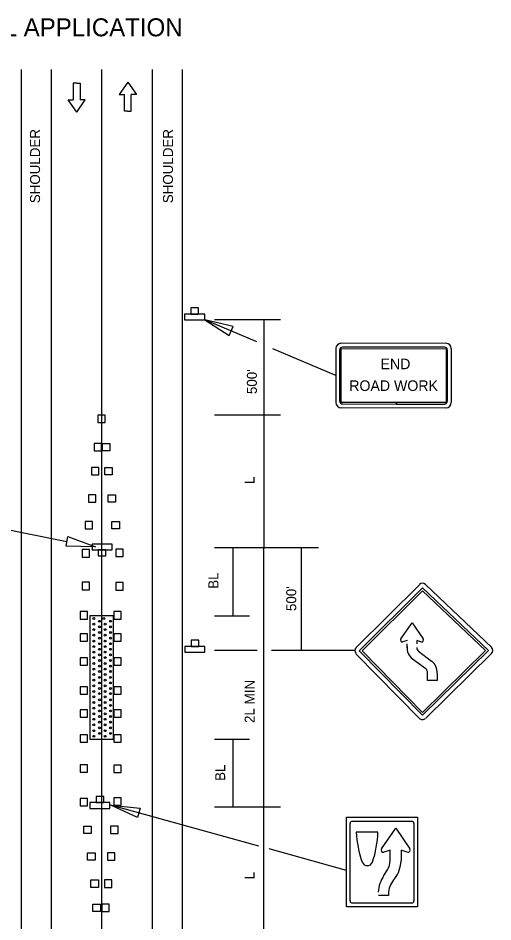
# Model space of a CAD drawing. Extents: x 612.48 to 619.85, y 611.03 to 621.02.
# Drawn here: x 616.73 to 619.58, y 615.59 to 621.02 of the extents above; entities that cross this region are included whole.
import ezdxf

# ---------------------------------------------------------------- set-up
doc = ezdxf.new("R2010")
doc.units = 0
for name, color, linetype in [('DETL-DIMS', 7, 'Continuous'), ('DETL-LINE', 7, 'Continuous'), ('DETL-NOTE', 7, 'Continuous'), ('DETL-TITL', 7, 'Continuous'), ('USER-BORD', 7, 'Continuous')]:
    doc.layers.add(name, color=color, linetype=linetype)

# ---------------------------------------------------------------- blocks, each defined once
blk = doc.blocks.new('TD')
at = {"layer": 'USER-BORD'}
for p, q in [((0, 0), (-0.0054, -0.0077)), ((0, 0), (0.0054, -0.0077)), ((-0.0054, -0.0077), (-0.0021, -0.0077)), ((-0.0021, -0.018), (-0.0021, -0.0077)), ((0.0021, -0.018), (0.0021, -0.0077)), ((0.0054, -0.0077), (0.0021, -0.0077)), ((-0.0002, -0.018), (-0.0021, -0.018)), ((-0.0002, -0.018), (0.0002, -0.018)), ((0.0002, -0.018), (0.0021, -0.018))]:
    blk.add_line(p, q, dxfattribs=at)

msp = doc.modelspace()

# ---------------------------------------------------------------- linework, layer by layer
at = {"layer": 'DETL-DIMS'}
for p, q in [((618.1645, 619.0756), (617.8515, 619.2089)), ((618.3066, 619.2089), (617.9108, 619.2089)), ((618.2067, 619.2089), (618.2067, 618.6361)), ((618.6389, 618.8737), (618.2597, 619.0351)), ((618.3066, 618.6361), (617.9108, 618.6361)), ((618.2067, 618.6361), (618.2067, 617.8375)), ((616.1861, 618.0434), (617.0233, 617.877)), ((618.5355, 617.8375), (617.9108, 617.8375)), ((618.0216, 617.429), (618.0216, 617.8375)), ((618.2067, 616.2804), (618.2067, 617.8375)), ((618.4333, 617.2208), (618.4333, 617.8375)), ((617.9108, 617.429), (618.121, 617.429)), ((618.1661, 617.2208), (617.9108, 617.2208)), ((618.754, 617.2208), (618.2518, 617.2208)), ((617.9108, 616.6888), (618.121, 616.6888)), ((618.0216, 616.2804), (618.0216, 616.6888)), ((618.1773, 616.0448), (617.2875, 616.2915)), ((617.9108, 616.2804), (618.3066, 616.2804)), ((618.2067, 615.4818), (618.2067, 616.2804)), ((618.7026, 615.8991), (618.2381, 616.0279))]:
    msp.add_line(p, q, dxfattribs=at)
for points in [[(617.9988, 619.1147), (618.0218, 619.1678), (617.8515, 619.2089)], [(617.0175, 617.8487), (617.0291, 617.9053), (617.194, 617.8431)], [(617.463, 616.2728), (617.4473, 616.2172), (617.2875, 616.2915)]]:
    msp.add_lwpolyline(points, close=True, dxfattribs=at)
at = {"layer": 'DETL-LINE'}
for p, q in [((616.7487, 620.7128), (616.7487, 612.917)), ((616.9288, 620.7128), (616.9288, 612.917)), ((617.232, 612.917), (617.232, 620.7128)), ((617.5352, 620.7128), (617.5352, 612.917)), ((617.7153, 620.7128), (617.7153, 612.917)), ((619.3014, 619.0673), (618.671, 619.068)), ((618.671, 619.0347), (619.302, 619.0353)), ((618.671, 618.7115), (618.671, 619.0347)), ((619.2918, 619.0436), (618.6799, 619.0449)), ((619.2918, 619.0436), (619.2918, 619.0436)), ((619.302, 619.0353), (619.3014, 618.7115)), ((618.662, 619.0264), (618.662, 618.7211)), ((619.3097, 618.7211), (619.3097, 619.0251)), ((619.0044, 618.7121), (618.671, 618.7115)), ((618.6806, 618.7032), (619.0038, 618.7025)), ((619.0038, 618.7025), (619.0044, 618.7121)), ((619.0044, 618.7121), (619.0038, 618.7025)), ((619.0038, 618.7025), (619.2924, 618.7025)), ((619.3014, 618.7115), (619.0044, 618.7121)), ((617.2436, 617.8294), (617.2436, 617.8294)), ((617.2436, 617.8294), (617.2436, 617.8294)), ((617.2436, 617.8294), (617.2436, 617.8294)), ((617.2436, 617.8294), (617.2436, 617.8294)), ((617.3032, 617.429), (617.1598, 617.429)), ((617.1598, 617.429), (617.1598, 616.6888)), ((617.1848, 617.4127), (617.1848, 617.4127)), ((617.2522, 617.4127), (617.2522, 617.4127)), ((617.3032, 616.6888), (617.3032, 617.429)), ((617.1848, 617.379), (617.1848, 617.379)), ((617.1848, 617.379), (617.1848, 617.379)), ((617.1848, 617.3463), (617.1848, 617.3463)), ((617.1848, 617.3463), (617.1848, 617.3463)), ((617.2185, 617.3964), (617.2185, 617.3964)), ((617.2185, 617.3636), (617.2185, 617.3636)), ((617.2185, 617.3636), (617.2185, 617.3636)), ((617.2522, 617.379), (617.2522, 617.379)), ((617.2522, 617.3463), (617.2522, 617.3463)), ((617.2523, 617.379), (617.2523, 617.379)), ((617.2523, 617.3463), (617.2523, 617.3463)), ((617.2859, 617.3964), (617.2859, 617.3964)), ((617.2859, 617.3636), (617.2859, 617.3636)), ((617.2859, 617.3636), (617.2859, 617.3636)), ((619.0297, 617.2918), (619.0969, 617.3872)), ((619.0969, 617.3872), (619.1641, 617.2918)), ((617.1848, 617.3126), (617.1848, 617.3126)), ((617.1848, 617.3126), (617.1848, 617.3126)), ((617.2185, 617.3289), (617.2185, 617.3289)), ((617.2185, 617.3289), (617.2185, 617.3289)), ((617.2185, 617.2952), (617.2185, 617.2952)), ((617.2185, 617.2952), (617.2185, 617.2952)), ((617.2522, 617.3126), (617.2522, 617.3126)), ((617.2523, 617.3126), (617.2523, 617.3126)), ((617.2859, 617.3289), (617.2859, 617.3289)), ((617.2859, 617.3289), (617.2859, 617.3289)), ((617.2859, 617.2952), (617.2859, 617.2952)), ((617.2859, 617.2952), (617.2859, 617.2952)), ((617.1848, 617.2779), (617.1848, 617.2779)), ((617.1848, 617.2779), (617.1848, 617.2779)), ((617.1848, 617.2442), (617.1848, 617.2442)), ((617.1848, 617.2442), (617.1848, 617.2442)), ((617.2185, 617.2616), (617.2185, 617.2616)), ((617.2185, 617.2616), (617.2185, 617.2616)), ((617.2522, 617.2779), (617.2522, 617.2779)), ((617.2522, 617.2442), (617.2522, 617.2442)), ((617.2523, 617.2779), (617.2523, 617.2779)), ((617.2523, 617.2442), (617.2523, 617.2442)), ((617.2859, 617.2616), (617.2859, 617.2616)), ((617.2859, 617.2616), (617.2859, 617.2616)), ((619.0674, 617.281), (619.0425, 617.2733)), ((619.0674, 617.2368), (619.0674, 617.2611)), ((619.1506, 617.2733), (619.1257, 617.281)), ((619.1257, 617.281), (619.1257, 617.2611)), ((617.1848, 617.2115), (617.1848, 617.2115)), ((617.1848, 617.2115), (617.1848, 617.2115)), ((617.2185, 617.2279), (617.2185, 617.2279)), ((617.2185, 617.2279), (617.2185, 617.2279)), ((617.2185, 617.1942), (617.2185, 617.1942)), ((617.2185, 617.1942), (617.2185, 617.1942)), ((617.2522, 617.2115), (617.2522, 617.2115)), ((617.2523, 617.2115), (617.2523, 617.2115)), ((617.2859, 617.2279), (617.2859, 617.2279)), ((617.2859, 617.2279), (617.2859, 617.2279)), ((617.2859, 617.1942), (617.2859, 617.1942)), ((617.2859, 617.1942), (617.2859, 617.1942)), ((619.1359, 617.217), (619.2146, 617.1568)), ((617.1848, 617.1778), (617.1848, 617.1778)), ((617.1848, 617.1778), (617.1848, 617.1778)), ((617.1848, 617.1432), (617.1848, 617.1432)), ((617.1848, 617.1432), (617.1848, 617.1432)), ((617.2185, 617.1605), (617.2185, 617.1605)), ((617.2185, 617.1605), (617.2185, 617.1605)), ((617.2185, 617.1268), (617.2185, 617.1268)), ((617.2185, 617.1268), (617.2185, 617.1268)), ((617.2522, 617.1778), (617.2522, 617.1778)), ((617.2522, 617.1432), (617.2522, 617.1432)), ((617.2523, 617.1778), (617.2523, 617.1778)), ((617.2523, 617.1432), (617.2523, 617.1432)), ((617.2859, 617.1605), (617.2859, 617.1605)), ((617.2859, 617.1605), (617.2859, 617.1605)), ((617.2859, 617.1268), (617.2859, 617.1268)), ((617.2859, 617.1268), (617.2859, 617.1268)), ((619.1794, 617.1107), (619.1007, 617.1696)), ((617.1848, 617.1095), (617.1848, 617.1095)), ((617.1848, 617.1095), (617.1848, 617.1095)), ((617.1848, 617.0768), (617.1848, 617.0768)), ((617.1848, 617.0768), (617.1848, 617.0768)), ((617.2185, 617.0941), (617.2185, 617.0941)), ((617.2185, 617.0941), (617.2185, 617.0941)), ((617.2522, 617.1095), (617.2522, 617.1095)), ((617.2522, 617.0768), (617.2522, 617.0768)), ((617.2523, 617.1095), (617.2523, 617.1095)), ((617.2523, 617.0768), (617.2523, 617.0768)), ((617.2859, 617.0941), (617.2859, 617.0941)), ((617.2859, 617.0941), (617.2859, 617.0941)), ((619.1897, 617.0403), (619.1897, 617.0941)), ((619.2479, 617.0832), (619.2479, 617.0403)), ((617.1848, 617.043), (617.1848, 617.043)), ((617.1848, 617.043), (617.1848, 617.043)), ((617.2185, 617.0594), (617.2185, 617.0594)), ((617.2185, 617.0594), (617.2185, 617.0594)), ((617.2185, 617.0258), (617.2185, 617.0258)), ((617.2185, 617.0258), (617.2185, 617.0258)), ((617.2522, 617.043), (617.2522, 617.043)), ((617.2523, 617.043), (617.2523, 617.043)), ((617.2859, 617.0594), (617.2859, 617.0594)), ((617.2859, 617.0594), (617.2859, 617.0594)), ((617.2859, 617.0258), (617.2859, 617.0258)), ((617.2859, 617.0258), (617.2859, 617.0258)), ((619.2479, 617.0403), (619.1897, 617.0403)), ((617.1848, 617.0084), (617.1848, 617.0084)), ((617.1848, 617.0084), (617.1848, 617.0084)), ((617.1848, 616.9747), (617.1848, 616.9747)), ((617.1848, 616.9747), (617.1848, 616.9747)), ((617.2185, 616.992), (617.2185, 616.992)), ((617.2185, 616.992), (617.2185, 616.992)), ((617.2522, 617.0084), (617.2522, 617.0084)), ((617.2522, 616.9747), (617.2522, 616.9747)), ((617.2523, 617.0084), (617.2523, 617.0084)), ((617.2523, 616.9747), (617.2523, 616.9747)), ((617.2859, 616.992), (617.2859, 616.992)), ((617.2859, 616.992), (617.2859, 616.992)), ((617.1848, 616.942), (617.1848, 616.942)), ((617.1848, 616.942), (617.1848, 616.942)), ((617.2178, 616.9615), (617.2178, 616.9615)), ((617.2185, 616.9583), (617.2185, 616.9583)), ((617.2185, 616.9247), (617.2185, 616.9247)), ((617.2185, 616.9247), (617.2185, 616.9247)), ((617.2522, 616.942), (617.2522, 616.942)), ((617.2523, 616.942), (617.2523, 616.942)), ((617.2852, 616.9615), (617.2852, 616.9615)), ((617.2859, 616.9583), (617.2859, 616.9583)), ((617.2859, 616.9247), (617.2859, 616.9247)), ((617.2859, 616.9247), (617.2859, 616.9247)), ((617.1848, 616.9083), (617.1848, 616.9083)), ((617.1848, 616.9083), (617.1848, 616.9083)), ((617.1848, 616.8737), (617.1848, 616.8737)), ((617.1848, 616.8737), (617.1848, 616.8737)), ((617.2185, 616.891), (617.2185, 616.891)), ((617.2185, 616.891), (617.2185, 616.891)), ((617.2185, 616.8573), (617.2185, 616.8573)), ((617.2185, 616.8573), (617.2185, 616.8573)), ((617.2522, 616.9083), (617.2522, 616.9083)), ((617.2522, 616.8737), (617.2522, 616.8737)), ((617.2523, 616.9083), (617.2523, 616.9083)), ((617.2523, 616.8737), (617.2523, 616.8737)), ((617.2859, 616.891), (617.2859, 616.891)), ((617.2859, 616.891), (617.2859, 616.891)), ((617.2859, 616.8573), (617.2859, 616.8573)), ((617.2859, 616.8573), (617.2859, 616.8573)), ((617.1848, 616.84), (617.1848, 616.84)), ((617.1848, 616.84), (617.1848, 616.84)), ((617.1848, 616.8072), (617.1848, 616.8072)), ((617.1848, 616.8072), (617.1848, 616.8072)), ((617.2185, 616.8246), (617.2185, 616.8246)), ((617.2185, 616.8246), (617.2185, 616.8246)), ((617.2522, 616.84), (617.2522, 616.84)), ((617.2522, 616.8072), (617.2522, 616.8072)), ((617.2523, 616.84), (617.2523, 616.84)), ((617.2523, 616.8072), (617.2523, 616.8072)), ((617.2859, 616.8246), (617.2859, 616.8246)), ((617.2859, 616.8246), (617.2859, 616.8246)), ((617.1848, 616.7736), (617.1848, 616.7736)), ((617.1848, 616.7736), (617.1848, 616.7736)), ((617.2185, 616.7899), (617.2185, 616.7899)), ((617.2185, 616.7899), (617.2185, 616.7899)), ((617.2185, 616.7562), (617.2185, 616.7562)), ((617.2185, 616.7562), (617.2185, 616.7562)), ((617.2522, 616.7736), (617.2522, 616.7736)), ((617.2523, 616.7736), (617.2523, 616.7736)), ((617.2859, 616.7899), (617.2859, 616.7899)), ((617.2859, 616.7899), (617.2859, 616.7899)), ((617.2859, 616.7562), (617.2859, 616.7562)), ((617.2859, 616.7562), (617.2859, 616.7562)), ((617.1848, 616.7389), (617.1848, 616.7389)), ((617.1848, 616.7389), (617.1848, 616.7389)), ((617.1848, 616.7052), (617.1848, 616.7052)), ((617.1848, 616.7052), (617.1848, 616.7052)), ((617.2185, 616.7226), (617.2185, 616.7226)), ((617.2185, 616.7226), (617.2185, 616.7226)), ((617.2522, 616.7389), (617.2522, 616.7389)), ((617.2522, 616.7052), (617.2522, 616.7052)), ((617.2523, 616.7389), (617.2523, 616.7389)), ((617.2523, 616.7052), (617.2523, 616.7052)), ((617.2859, 616.7226), (617.2859, 616.7226)), ((617.2859, 616.7226), (617.2859, 616.7226)), ((617.1598, 616.6888), (617.3032, 616.6888)), ((617.2194, 616.2884), (617.2194, 616.2884)), ((617.2194, 616.2884), (617.2194, 616.2884)), ((617.2194, 616.2884), (617.2194, 616.2884)), ((617.2194, 616.2884), (617.2194, 616.2884)), ((618.7026, 616.2182), (619.1307, 616.2182)), ((618.7026, 615.68), (618.7026, 616.2182)), ((619.1307, 616.2182), (619.1307, 615.68)), ((618.9131, 616.0288), (618.9989, 616.1536)), ((618.9989, 616.1536), (619.084, 616.0288)), ((618.7614, 616.1299), (618.892, 616.1299)), ((618.7614, 616.1299), (618.7614, 616.1299)), ((618.9662, 616.0211), (618.9278, 616.0089)), ((618.9662, 615.9564), (618.9662, 616.0211)), ((619.0686, 616.0089), (619.0315, 616.0211)), ((619.0315, 616.0211), (619.0315, 615.9564)), ((618.9278, 615.8675), (618.9502, 615.902)), ((618.956, 615.7689), (618.956, 615.7472)), ((618.956, 615.7472), (618.8946, 615.7472)), ((619.1307, 615.68), (618.7026, 615.68))]:
    msp.add_line(p, q, dxfattribs=at)
for points in [[(617.232, 620.642), (617.232, 620.7128)], [(617.232, 620.117), (617.232, 620.192)], [(617.232, 620.042), (617.232, 620.117)], [(617.232, 619.517), (617.232, 619.592)], [(617.232, 619.442), (617.232, 619.517)], [(618.639, 619.0353), (618.639, 618.7121)], [(619.3334, 618.7115), (619.3334, 619.036)], [(617.232, 618.917), (617.232, 618.992)], [(617.232, 618.842), (617.232, 618.917)], [(618.6716, 618.6808), (619.3014, 618.6801)], [(617.232, 618.317), (617.232, 618.392)], [(617.232, 618.242), (617.232, 618.317)], [(617.232, 617.717), (617.232, 617.792)], [(617.232, 617.642), (617.232, 617.717)], [(619.141, 617.6163), (618.7615, 617.2387)], [(619.5762, 617.2381), (619.1775, 617.617)], [(618.7801, 617.2195), (619.159, 617.5984)], [(618.7974, 617.2195), (619.159, 617.5805)], [(619.159, 617.5984), (619.5564, 617.2202)], [(619.159, 617.5805), (619.5378, 617.2208)], [(617.232, 617.117), (617.232, 617.192)], [(618.7602, 617.2016), (619.141, 616.8125)], [(619.1596, 616.8317), (618.7801, 617.2195)], [(619.1609, 616.849), (618.7974, 617.2195)], [(619.5564, 617.2202), (619.1596, 616.8317)], [(619.5378, 617.2208), (619.1609, 616.849)], [(619.1794, 616.8131), (619.575, 617.2022)], [(617.232, 617.042), (617.232, 617.117)], [(617.232, 616.517), (617.232, 616.592)], [(617.232, 616.442), (617.232, 616.517)], [(618.7256, 615.7158), (618.7256, 616.1811)], [(618.739, 616.1952), (619.0949, 616.1952)], [(619.1083, 616.1811), (619.1083, 615.7158)], [(617.232, 615.917), (617.232, 615.992)], [(617.232, 615.842), (617.232, 615.917)], [(619.0949, 615.7024), (618.739, 615.7024)]]:
    msp.add_lwpolyline(points, dxfattribs=at)
for points in [[(617.768, 619.2435), (617.8142, 619.2435), (617.8142, 619.2802), (617.768, 619.2802)], [(617.7303, 619.2435), (617.7303, 619.2089), (617.8515, 619.2089), (617.8515, 619.2435)], [(617.2088, 618.5913), (617.2536, 618.5913), (617.2536, 618.6361), (617.2088, 618.6361)], [(617.1868, 618.4212), (617.2316, 618.4212), (617.2316, 618.466), (617.1868, 618.466)], [(617.2816, 618.4212), (617.2368, 618.4212), (617.2368, 618.466), (617.2816, 618.466)], [(617.1703, 618.2761), (617.2151, 618.2761), (617.2151, 618.3209), (617.1703, 618.3209)], [(617.2953, 618.2761), (617.2505, 618.2761), (617.2505, 618.3209), (617.2953, 618.3209)], [(617.1518, 618.1128), (617.1966, 618.1128), (617.1966, 618.1576), (617.1518, 618.1576)], [(617.3156, 618.1128), (617.2708, 618.1128), (617.2708, 618.1576), (617.3156, 618.1576)], [(617.1326, 617.9522), (617.1774, 617.9522), (617.1774, 617.997), (617.1326, 617.997)], [(617.3382, 617.9522), (617.2934, 617.9522), (617.2934, 617.997), (617.3382, 617.997)], [(617.2953, 617.8262), (617.2953, 617.8608), (617.1741, 617.8608), (617.1741, 617.8262)], [(617.1586, 617.8275), (617.1138, 617.8275), (617.1138, 617.7827), (617.1586, 617.7827)], [(617.2577, 617.8262), (617.2114, 617.8262), (617.2114, 617.7896), (617.2577, 617.7896)], [(617.3608, 617.831), (617.316, 617.831), (617.316, 617.7862), (617.3608, 617.7862)], [(617.1586, 617.631), (617.1138, 617.631), (617.1138, 617.5862), (617.1586, 617.5862)], [(617.3608, 617.6293), (617.316, 617.6293), (617.316, 617.5845), (617.3608, 617.5845)], [(617.1022, 617.4098), (617.147, 617.4098), (617.147, 617.4546), (617.1022, 617.4546)], [(617.3044, 617.4098), (617.3492, 617.4098), (617.3492, 617.4546), (617.3044, 617.4546)], [(617.1022, 617.277), (617.147, 617.277), (617.147, 617.3218), (617.1022, 617.3218)], [(617.3044, 617.277), (617.3492, 617.277), (617.3492, 617.3218), (617.3044, 617.3218)], [(617.7311, 617.2456), (617.7311, 617.211), (617.8523, 617.211), (617.8523, 617.2456)], [(617.7688, 617.2456), (617.815, 617.2456), (617.815, 617.2822), (617.7688, 617.2822)], [(617.1022, 617.1326), (617.147, 617.1326), (617.147, 617.1774), (617.1022, 617.1774)], [(617.3044, 617.1326), (617.3492, 617.1326), (617.3492, 617.1774), (617.3044, 617.1774)], [(617.1022, 616.9583), (617.147, 616.9583), (617.147, 617.0031), (617.1022, 617.0031)], [(617.3044, 616.9583), (617.3492, 616.9583), (617.3492, 617.0031), (617.3044, 617.0031)], [(617.1022, 616.8198), (617.147, 616.8198), (617.147, 616.8646), (617.1022, 616.8646)], [(617.3044, 616.8198), (617.3492, 616.8198), (617.3492, 616.8646), (617.3044, 616.8646)], [(617.1022, 616.6696), (617.147, 616.6696), (617.147, 616.7144), (617.1022, 616.7144)], [(617.3044, 616.6696), (617.3492, 616.6696), (617.3492, 616.7144), (617.3044, 616.7144)], [(617.1022, 616.4886), (617.147, 616.4886), (617.147, 616.5334), (617.1022, 616.5334)], [(617.3044, 616.4868), (617.3492, 616.4868), (617.3492, 616.5316), (617.3044, 616.5316)], [(617.1022, 616.2869), (617.147, 616.2869), (617.147, 616.3317), (617.1022, 616.3317)], [(617.1981, 616.3065), (617.2444, 616.3065), (617.2444, 616.3432), (617.1981, 616.3432)], [(617.3044, 616.2904), (617.3492, 616.2904), (617.3492, 616.3352), (617.3044, 616.3352)], [(617.1605, 616.3065), (617.1605, 616.2719), (617.2817, 616.2719), (617.2817, 616.3065)], [(617.1248, 616.1656), (617.1696, 616.1656), (617.1696, 616.1208), (617.1248, 616.1208)], [(617.3304, 616.1656), (617.2856, 616.1656), (617.2856, 616.1208), (617.3304, 616.1208)], [(617.1474, 616.005), (617.1922, 616.005), (617.1922, 615.9602), (617.1474, 615.9602)], [(617.3112, 616.005), (617.2664, 616.005), (617.2664, 615.9602), (617.3112, 615.9602)], [(617.1677, 615.8418), (617.2125, 615.8418), (617.2125, 615.797), (617.1677, 615.797)], [(617.2927, 615.8418), (617.2479, 615.8418), (617.2479, 615.797), (617.2927, 615.797)], [(617.1797, 615.6966), (617.2245, 615.6966), (617.2245, 615.6518), (617.1797, 615.6518)], [(617.2778, 615.6966), (617.233, 615.6966), (617.233, 615.6518), (617.2778, 615.6518)]]:
    msp.add_lwpolyline(points, close=True, dxfattribs=at)
for centre in [(617.1848, 617.4127), (617.2185, 617.3964), (617.2454, 617.4127), (617.2859, 617.3964), (617.1848, 617.379), (617.1848, 617.3463), (617.2185, 617.3636), (617.2523, 617.379), (617.2523, 617.3463), (617.2859, 617.3636), (617.1848, 617.3126), (617.2185, 617.3289), (617.2185, 617.2952), (617.2523, 617.3126), (617.2859, 617.3289), (617.2859, 617.2952), (617.1848, 617.2779), (617.1848, 617.2442), (617.2185, 617.2616), (617.2523, 617.2779), (617.2523, 617.2442), (617.2859, 617.2616), (617.1848, 617.2115), (617.1848, 617.1778), (617.2185, 617.2279), (617.2185, 617.1942), (617.2523, 617.2115), (617.2523, 617.1778), (617.2859, 617.2279), (617.2859, 617.1942), (617.1848, 617.1432), (617.2185, 617.1605), (617.2185, 617.1268), (617.2523, 617.1432), (617.2859, 617.1605), (617.2859, 617.1268), (617.1848, 617.1095), (617.1848, 617.0768), (617.2185, 617.0941), (617.2523, 617.1095), (617.2523, 617.0768), (617.2859, 617.0941), (617.1848, 617.043), (617.2185, 617.0594), (617.2185, 617.0258), (617.2523, 617.043), (617.2859, 617.0594), (617.2859, 617.0258), (617.1848, 617.0084), (617.1848, 616.9747), (617.2178, 616.9615), (617.2185, 616.992), (617.2523, 617.0084), (617.2523, 616.9747), (617.2852, 616.9615), (617.2859, 616.992), (617.1848, 616.942), (617.1848, 616.9083), (617.2185, 616.9247), (617.2523, 616.942), (617.2523, 616.9083), (617.2859, 616.9247), (617.1848, 616.8737), (617.2185, 616.891), (617.2185, 616.8573), (617.2523, 616.8737), (617.2859, 616.891), (617.2859, 616.8573), (617.1848, 616.84), (617.1848, 616.8072), (617.2185, 616.8246), (617.2523, 616.84), (617.2523, 616.8072), (617.2859, 616.8246), (617.1848, 616.7736), (617.2185, 616.7899), (617.2185, 616.7562), (617.2523, 616.7736), (617.2859, 616.7899), (617.2859, 616.7562), (617.1848, 616.7389), (617.1848, 616.7052), (617.2185, 616.7226), (617.2523, 616.7389), (617.2523, 616.7052), (617.2859, 616.7226)]:
    msp.add_circle(centre, 0.00564, dxfattribs=at)
for centre, radius, start, end in [((618.6709, 619.0356), 0.032, 90, 180), ((618.6799, 619.0266), 0.018, 90, 180), ((619.2922, 619.0266), 0.018, 0, 90), ((619.3011, 619.0356), 0.032, 0, 90), ((618.6709, 618.712), 0.032, 180, 270), ((618.6799, 618.721), 0.018, 180, 270), ((619.2922, 618.721), 0.018, 270, 0), ((619.3011, 618.712), 0.032, 270, 0), ((619.1596, 617.5987), 0.026, 47.7263, 133.5312), ((619.0391, 617.2848), 0.0117, 145.0005, 287.9921), ((619.1541, 617.2847), 0.0117, 251.9923, 35.0014), ((618.78, 617.2202), 0.026, 135, 222.5104), ((619.1507, 617.237), 0.0836, 175.1429, 233.1855), ((619.1507, 617.237), 0.0251, 177.0594, 233.1855), ((619.5571, 617.2209), 0.026, 315, 45), ((619.1645, 617.0908), 0.0836, 355.1914, 53.1853), ((619.1645, 617.0908), 0.0251, 7.1191, 53.1531), ((619.1603, 616.8314), 0.026, 220.6013, 315), ((618.7387, 616.1809), 0.0137, 90, 180), ((619.0943, 616.1809), 0.0137, 0, 90), ((619.3568, 616.1562), 0.5961, 182.5529, 200.3658), ((618.2947, 616.1439), 0.5972, 340.9328, 358.6381), ((618.9239, 616.021), 0.0128, 145.7397, 288), ((619.0729, 616.021), 0.0128, 252, 34.2603), ((618.8285, 615.9601), 0.0326, 200.3641, 339.6359), ((618.8356, 615.9646), 0.1304, 331.1838, 356.1678), ((618.8356, 615.9646), 0.1955, 324.1907, 357.4446), ((619.0873, 615.7575), 0.1938, 145.3872, 176.6343), ((619.0873, 615.7575), 0.1314, 135.1307, 175.032), ((618.7387, 615.7158), 0.0137, 180, 270), ((619.0943, 615.7158), 0.0137, 270, 0)]:
    msp.add_arc(centre, radius, start, end, dxfattribs=at)

# ---------------------------------------------------------------- block references
at = {"layer": 'DETL-LINE', "xscale": 9.625616, "yscale": 9.625616, "rotation": 180}
msp.add_blockref('TD', (617.0816, 620.4574), dxfattribs=at)
at = {"layer": 'DETL-LINE', "xscale": 9.625616, "yscale": 9.625616}
msp.add_blockref('TD', (617.3895, 620.6368), dxfattribs=at)

# ---------------------------------------------------------------- texts
at = {"layer": 'DETL-LINE'}
for s, p in [('END', (618.9078, 618.9118)), ('ROAD WORK', (618.7197, 618.7812))]:
    msp.add_text(s, height=0.06352, dxfattribs=at).set_placement(p)
at = {"layer": 'DETL-NOTE'}
for s, p in [('SHOULDER', (616.8615, 619.9098)), ('SHOULDER', (617.6604, 619.9098)), ("500'", (618.1645, 618.7624)), ('L', (618.1509, 618.2214)), ('BL', (617.9332, 617.5919)), ("500'", (618.401, 617.458)), ('2L MIN', (618.1509, 616.7853)), ('BL', (617.9744, 616.437)), ('L', (618.1509, 615.8452))]:
    msp.add_text(s, height=0.06, rotation=90, dxfattribs=at).set_placement(p)
at = {"layer": 'DETL-TITL'}
msp.add_text('TEMPORARY TRAFFIC CONTROL TYPICAL APPLICATION', height=0.108, dxfattribs=at).set_placement((613.7702, 620.913))

doc.saveas('drawing.dxf')
